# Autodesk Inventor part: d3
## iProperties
Created: 2002-02
Part Number: d3
Document SubType Name: ﾓﾃﾞﾘﾝｸﾞ
Designer: Administrator
Control State: 0
Master: False
Checked Out: False
Shininess: 64.0
Length Units: 11269
Angle Units: 11279
Time Units: 11290
Mass Units: 11284
Length Display Precision: 2
Angle Display Precision: 1
Density: 0.0
Volumn: 0.0
Area: 0.0
PropertySet Name: Model Information
Author: Administrator
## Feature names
1. 押し出し6 [Extrusion]
